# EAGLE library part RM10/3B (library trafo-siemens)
TRANSFORMER
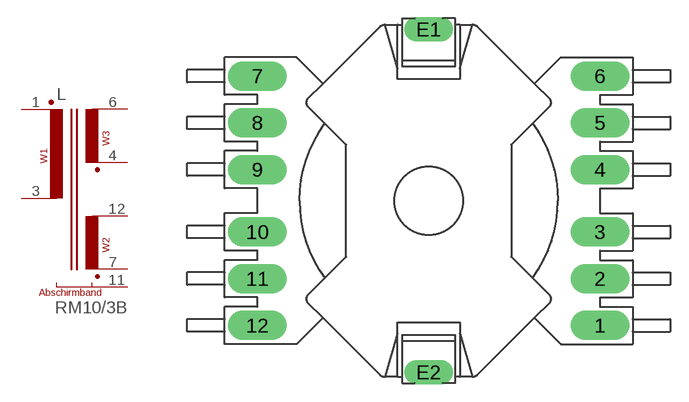
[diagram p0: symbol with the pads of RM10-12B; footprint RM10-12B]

Designator prefix L

## RM10/3B  [RM10-12B]
1  1A  pas
3  1E  pas
4  3A  pas
6  3E  pas
7  2A  pas
11  SCH  pas
12  2E  pas

## Footprint RM10-12B (pad centres in mm)
TRANSFORMER
drill 1.6 long: 1 13.97,-10.16; 2 13.97,-6.35; 3 13.97,-2.54; 4 13.97,2.54; 5 13.97,6.35; 6 13.97,10.16; 7 -13.97,10.16; 8 -13.97,6.35; 9 -13.97,2.54; 10 -13.97,-2.54; 11 -13.97,-6.35; 12 -13.97,-10.16
drill 1.321 long: E1 0,13.97; E2 0,-13.97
